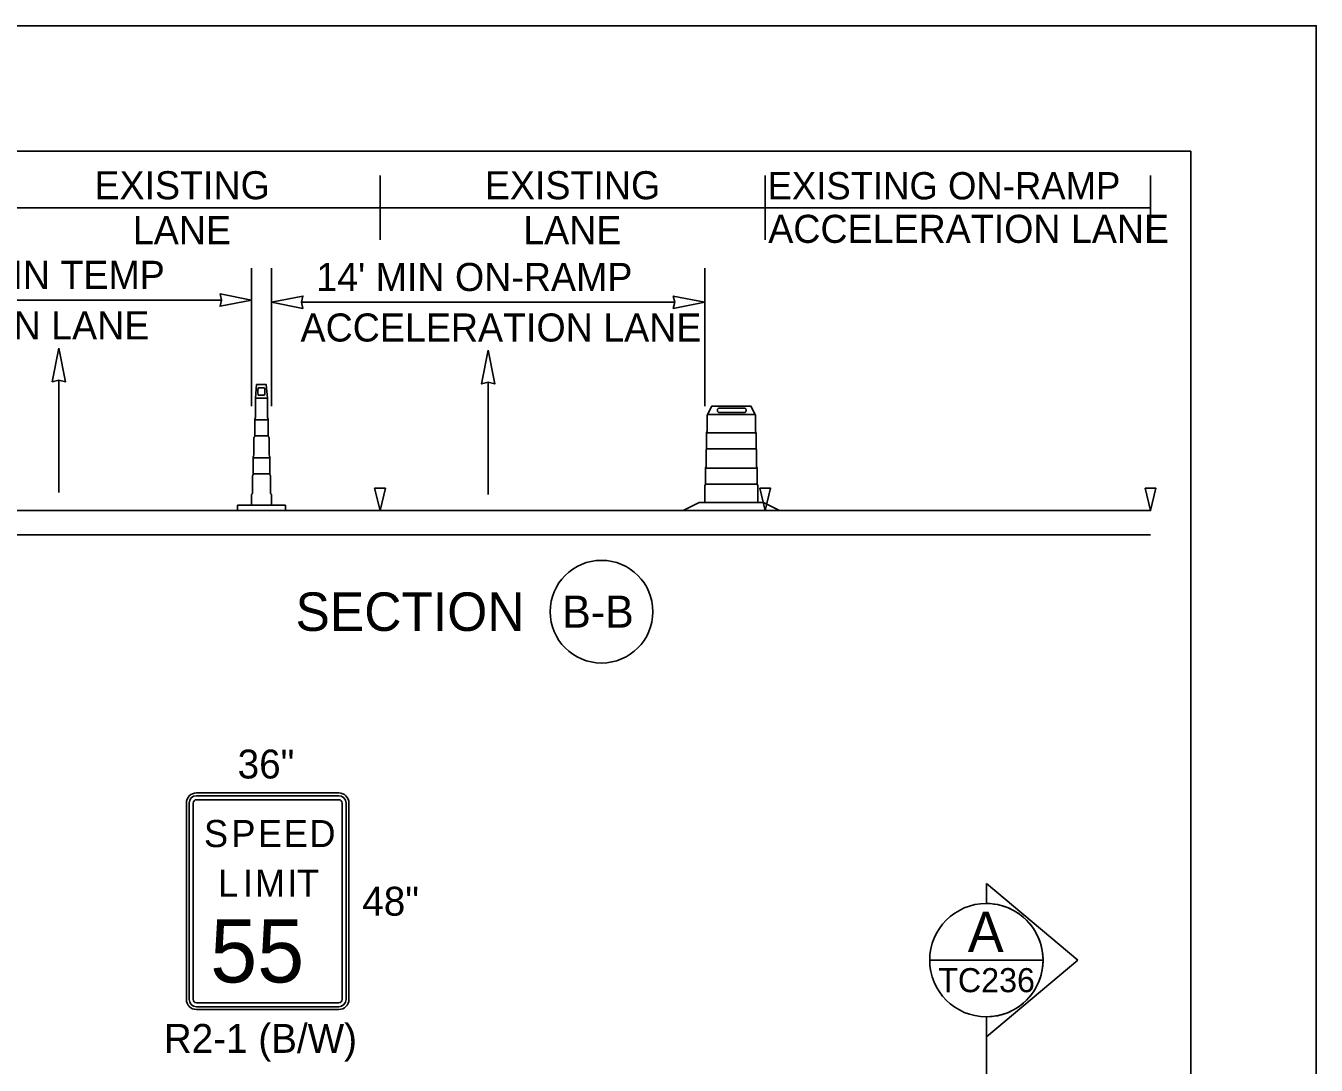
# Model space of a CAD drawing. Extents: x 99999 to 100116, y 99995 to 100013.
# Drawn here: x 100072.847 to 100076.062, y 100008.096 to 100010.687 of the extents above; entities that cross this region are included whole.
import ezdxf

# ---------------------------------------------------------------- set-up
doc = ezdxf.new("R2010")
doc.units = 0
for name, color, linetype in [('SH_GI_PlotLimits', 7, 'Continuous'), ('SH_GI_SheetBorder', 7, 'Continuous'), ('SH_TI_WZSectionCut', 7, 'Continuous'), ('TR_SN_ConstructionSigns', 7, 'Continuous'), ('TR_WZ_ArrowLeftStrRightTurn', 7, 'Continuous'), ('TR_WZ_TallChanDeviceElev', 7, 'Continuous'), ('TR_WZ_TrafficSafetyDrumElev', 7, 'Continuous'), ('TR_WZ_WorkZoneDetails', 7, 'Continuous')]:
    doc.layers.add(name, color=color, linetype=linetype)

msp = doc.modelspace()

# ---------------------------------------------------------------- linework, layer by layer
at = {"layer": 'SH_GI_PlotLimits'}
msp.add_lwpolyline([(100059.0625, 99999.6875), (100076.0625, 99999.6875), (100076.0625, 100010.6875), (100059.0625, 100010.6875)], close=True, dxfattribs=at)
at = {"layer": 'SH_GI_SheetBorder'}
for p, q in [((100060, 100010.375), (100075.75, 100010.375)), ((100075.75, 100010.375), (100075.75, 100000))]:
    msp.add_line(p, q, dxfattribs=at)
at = {"layer": 'SH_TI_WZSectionCut'}
for p, q in [((100073.41, 100009.7388), (100073.41, 100010.0836)), ((100072.525, 100010.0036), (100073.335, 100010.0036)), ((100075.2407, 100008.4993), (100075.2407, 100008.5492)), ((100075.2407, 100008.5492), (100075.4688, 100008.358)), ((100075.4688, 100008.358), (100075.2407, 100008.1669)), ((100075.2407, 100008.1669), (100075.2407, 100008.2168)), ((100075.2407, 100008.1669), (100075.2407, 100006.4389))]:
    msp.add_line(p, q, dxfattribs=at)
msp.add_lwpolyline([(100073.41, 100010.0036), (100073.3314, 100009.9882), (100073.335, 100010.0036), (100073.3314, 100010.019)], close=True, dxfattribs=at)
msp.add_lwpolyline([(100075.0995, 100008.3581), (100075.3819, 100008.3581)], dxfattribs=at)
msp.add_circle((100075.2407, 100008.358), 0.1412, dxfattribs=at)
msp.add_arc((100075.2407, 100008.358), 0.1412, 269.9978, 90.0022, dxfattribs=at)
at = {"layer": 'TR_SN_ConstructionSigns'}
for p, q in [((100073.2728, 100008.7749), (100073.6272, 100008.7749)), ((100073.6272, 100008.7749), (100073.2728, 100008.7749)), ((100073.6272, 100008.7679), (100073.2728, 100008.7679)), ((100073.2728, 100008.758), (100073.6272, 100008.758)), ((100073.2475, 100008.2602), (100073.2475, 100008.7496)), ((100073.2475, 100008.7496), (100073.2475, 100008.2602)), ((100073.2546, 100008.7496), (100073.2546, 100008.2602)), ((100073.2644, 100008.2602), (100073.2644, 100008.7496)), ((100073.6357, 100008.7496), (100073.6357, 100008.2602)), ((100073.6455, 100008.2602), (100073.6455, 100008.7496)), ((100073.6525, 100008.7496), (100073.6525, 100008.2602)), ((100073.6525, 100008.2602), (100073.6525, 100008.7496)), ((100073.6272, 100008.2518), (100073.2728, 100008.2518)), ((100073.2728, 100008.2419), (100073.6272, 100008.2419)), ((100073.6272, 100008.2349), (100073.2728, 100008.2349)), ((100073.2728, 100008.2349), (100073.6272, 100008.2349))]:
    msp.add_line(p, q, dxfattribs=at)
for centre, radius, start, end in [((100073.2728, 100008.7496), 0.0253, 90, 180), ((100073.2728, 100008.7496), 0.0253, 90, 180), ((100073.2728, 100008.7496), 0.0183, 90, 180), ((100073.2728, 100008.7496), 0.00844, 90, 180), ((100073.6272, 100008.7496), 0.0253, 360, 90), ((100073.6272, 100008.7496), 0.0253, 360, 90), ((100073.6272, 100008.7496), 0.0183, 0, 90), ((100073.6272, 100008.7496), 0.00844, 360, 90), ((100073.2728, 100008.2602), 0.0253, 180, 270), ((100073.2728, 100008.2602), 0.0253, 180, 270), ((100073.2728, 100008.2602), 0.0183, 180, 270), ((100073.2728, 100008.2602), 0.00844, 180, 270), ((100073.6272, 100008.2602), 0.0253, 270, 360), ((100073.6272, 100008.2602), 0.0183, 270, 360), ((100073.6272, 100008.2602), 0.00844, 270, 0), ((100073.6272, 100008.2602), 0.0253, 270, 360)]:
    msp.add_arc(centre, radius, start, end, dxfattribs=at)
at = {"layer": 'TR_WZ_ArrowLeftStrRightTurn'}
for p, q in [((100072.93, 100009.8039), (100072.93, 100009.524)), ((100073.9994, 100009.7986), (100073.9994, 100009.5187))]:
    msp.add_line(p, q, dxfattribs=at)
for points in [[(100072.93, 100009.884), (100072.9135, 100009.8), (100072.93, 100009.8039), (100072.9465, 100009.8)], [(100073.9994, 100009.8787), (100073.9829, 100009.7947), (100073.9994, 100009.7986), (100074.0159, 100009.7947)]]:
    msp.add_lwpolyline(points, close=True, dxfattribs=at)
at = {"layer": 'TR_WZ_TallChanDeviceElev'}
for p, q in [((100073.4422, 100009.7848), (100073.4266, 100009.7848)), ((100073.4494, 100009.7588), (100073.42, 100009.7588)), ((100073.42, 100009.7588), (100073.4494, 100009.7588)), ((100073.42, 100009.7588), (100073.4494, 100009.7588)), ((100073.4266, 100009.767), (100073.4422, 100009.767)), ((100073.4178, 100009.7051), (100073.4515, 100009.7051)), ((100073.4178, 100009.6655), (100073.4178, 100009.7051)), ((100073.4515, 100009.7051), (100073.4515, 100009.6655)), ((100073.4515, 100009.6655), (100073.4178, 100009.6655)), ((100073.4139, 100009.5707), (100073.4139, 100009.6103)), ((100073.4139, 100009.6103), (100073.4555, 100009.6103)), ((100073.4555, 100009.6103), (100073.4555, 100009.5707)), ((100073.4555, 100009.5707), (100073.4139, 100009.5707)), ((100073.3747, 100009.4788), (100073.3747, 100009.492)), ((100073.4947, 100009.4788), (100073.3747, 100009.4788)), ((100073.4947, 100009.492), (100073.4947, 100009.4788))]:
    msp.add_line(p, q, dxfattribs=at)
for points in [[(100073.4494, 100009.7588), (100073.4467, 100009.793), (100073.4225, 100009.793), (100073.42, 100009.7588)], [(100073.4515, 100009.7051), (100073.4178, 100009.7051), (100073.4178, 100009.6655), (100073.4515, 100009.6655)], [(100073.4555, 100009.6103), (100073.4139, 100009.6103), (100073.4139, 100009.5707), (100073.4555, 100009.5707)]]:
    msp.add_lwpolyline(points, close=True, dxfattribs=at)
for points in [[(100073.4198, 100009.7106), (100073.4198, 100009.7555)], [(100073.4198, 100009.7106), (100073.4198, 100009.7555)], [(100073.4496, 100009.7555), (100073.4496, 100009.7106)], [(100073.4496, 100009.7555), (100073.4496, 100009.7106)], [(100073.4178, 100009.6632), (100073.4178, 100009.7074)], [(100073.4178, 100009.6632), (100073.4178, 100009.7074)], [(100073.4515, 100009.7074), (100073.4515, 100009.6632)], [(100073.4515, 100009.7074), (100073.4515, 100009.6632)], [(100073.4159, 100009.6158), (100073.4159, 100009.66)], [(100073.4159, 100009.6158), (100073.4159, 100009.66)], [(100073.4535, 100009.66), (100073.4535, 100009.6158)], [(100073.4535, 100009.66), (100073.4535, 100009.6158)], [(100073.4139, 100009.5685), (100073.4139, 100009.6125)], [(100073.4139, 100009.5685), (100073.4139, 100009.6125)], [(100073.4555, 100009.6125), (100073.4555, 100009.5685)], [(100073.4555, 100009.6125), (100073.4555, 100009.5685)], [(100073.412, 100009.5212), (100073.412, 100009.5653)], [(100073.412, 100009.5212), (100073.412, 100009.5653)], [(100073.4574, 100009.5653), (100073.4574, 100009.5212)], [(100073.4574, 100009.5653), (100073.4574, 100009.5212)], [(100073.4594, 100009.492), (100073.41, 100009.492), (100073.41, 100009.518)], [(100073.4594, 100009.492), (100073.41, 100009.492), (100073.41, 100009.518)], [(100073.4594, 100009.518), (100073.4594, 100009.492)], [(100073.4594, 100009.518), (100073.4594, 100009.492)], [(100073.3747, 100009.492), (100073.41, 100009.492), (100073.4594, 100009.492), (100073.4947, 100009.492)]]:
    msp.add_lwpolyline(points, dxfattribs=at)
for centre, major_axis, ratio, start_param, end_param in [((100073.4266, 100009.7759), (0, 0.00891), 0.07945, 0, 3.141593), ((100073.4422, 100009.7759), (0, 0.00891), 0.07945, 3.141593, 6.283185), ((100073.42, 100009.7548), (0, 0.00412), 0.059356, 0.177149, 1.393647), ((100073.42, 100009.7548), (0, 0.00412), 0.059356, 0.177149, 1.393647), ((100073.4493, 100009.7548), (0, 0.00412), 0.059356, 4.889538, 6.106036), ((100073.4493, 100009.7548), (0, 0.00412), 0.059356, 4.889538, 6.106036), ((100073.4214, 100009.7047), (0, 0.00651), 0.609371, 0.4288, 1.141997), ((100073.4214, 100009.7047), (0, 0.00651), 0.609371, 0.4288, 1.141997), ((100073.4479, 100009.7047), (0, 0.00651), 0.609371, 5.141189, 5.854386), ((100073.4479, 100009.7047), (0, 0.00651), 0.609371, 5.141189, 5.854386), ((100073.4195, 100009.6573), (0, 0.00651), 0.609371, 0.4288, 1.141997), ((100073.4195, 100009.6573), (0, 0.00651), 0.609371, 0.4288, 1.141997), ((100073.4499, 100009.6573), (0, 0.00651), 0.609371, 5.141189, 5.854386), ((100073.4499, 100009.6573), (0, 0.00651), 0.609371, 5.141189, 5.854386), ((100073.4175, 100009.6098), (0, 0.00651), 0.609371, 0.4288, 1.141997), ((100073.4175, 100009.6098), (0, 0.00651), 0.609371, 0.4288, 1.141997), ((100073.4519, 100009.6098), (0, 0.00651), 0.609371, 5.141189, 5.854386), ((100073.4519, 100009.6098), (0, 0.00651), 0.609371, 5.141189, 5.854386), ((100073.4156, 100009.5625), (0, 0.00651), 0.609371, 0.4288, 1.141997), ((100073.4156, 100009.5625), (0, 0.00651), 0.609371, 0.4288, 1.141997), ((100073.4538, 100009.5625), (0, 0.00651), 0.609371, 5.141189, 5.854386), ((100073.4538, 100009.5625), (0, 0.00651), 0.609371, 5.141189, 5.854386), ((100073.4136, 100009.5153), (0, 0.00651), 0.609371, 0.4288, 1.141997), ((100073.4136, 100009.5153), (0, 0.00651), 0.609371, 0.4288, 1.141997), ((100073.4558, 100009.5153), (0, 0.00651), 0.609371, 5.141189, 5.854386), ((100073.4558, 100009.5153), (0, 0.00651), 0.609371, 5.141189, 5.854386)]:
    msp.add_ellipse(centre, major_axis=major_axis, ratio=ratio, start_param=start_param, end_param=end_param, dxfattribs=at)
at = {"layer": 'TR_WZ_TrafficSafetyDrumElev'}
for p, q in [((100074.5737, 100009.734), (100074.6391, 100009.734)), ((100074.6391, 100009.7236), (100074.5737, 100009.7236)), ((100074.5461, 100009.7188), (100074.6645, 100009.7188)), ((100074.5461, 100009.7188), (100074.6645, 100009.7188)), ((100074.5438, 100009.6724), (100074.6668, 100009.6724)), ((100074.5438, 100009.6325), (100074.5438, 100009.6724)), ((100074.6668, 100009.6724), (100074.6668, 100009.6325)), ((100074.6668, 100009.6325), (100074.5438, 100009.6325)), ((100074.5409, 100009.5844), (100074.6697, 100009.5844)), ((100074.5409, 100009.5445), (100074.5409, 100009.5844)), ((100074.6697, 100009.5844), (100074.6697, 100009.5445)), ((100074.6697, 100009.5445), (100074.5409, 100009.5445))]:
    msp.add_line(p, q, dxfattribs=at)
for points in [[(100074.6645, 100009.7188), (100074.654, 100009.7388), (100074.5566, 100009.7388), (100074.5461, 100009.7188)], [(100074.4853, 100009.4788), (100074.5255, 100009.4988), (100074.6851, 100009.4988), (100074.7253, 100009.4788)]]:
    msp.add_lwpolyline(points, close=True, dxfattribs=at)
for points in [[(100074.5453, 100009.676), (100074.5453, 100009.7172)], [(100074.5453, 100009.676), (100074.5453, 100009.7172)], [(100074.6653, 100009.7172), (100074.6653, 100009.676)], [(100074.6653, 100009.7172), (100074.6653, 100009.676)], [(100074.5438, 100009.632), (100074.5438, 100009.673)], [(100074.5438, 100009.632), (100074.5438, 100009.673)], [(100074.6668, 100009.673), (100074.6668, 100009.632)], [(100074.6668, 100009.673), (100074.6668, 100009.632)], [(100074.5423, 100009.5879), (100074.5423, 100009.629)], [(100074.5423, 100009.5879), (100074.5423, 100009.629)], [(100074.6682, 100009.629), (100074.6682, 100009.5879)], [(100074.6682, 100009.629), (100074.6682, 100009.5879)], [(100074.5409, 100009.5439), (100074.5409, 100009.5849)], [(100074.5409, 100009.5439), (100074.5409, 100009.5849)], [(100074.6697, 100009.5849), (100074.6697, 100009.5439)], [(100074.6697, 100009.5849), (100074.6697, 100009.5439)], [(100074.6712, 100009.5409), (100074.6712, 100009.4988), (100074.5394, 100009.4988), (100074.5394, 100009.5409)], [(100074.6712, 100009.5409), (100074.6712, 100009.4988), (100074.5394, 100009.4988), (100074.5394, 100009.5409)]]:
    msp.add_lwpolyline(points, dxfattribs=at)
for centre, major_axis, ratio, start_param, end_param in [((100074.5737, 100009.7288), (0, 0.0052), 0.570305, 0, 3.141593), ((100074.6391, 100009.7288), (0, 0.0052), 0.570305, 3.141593, 6.283185), ((100074.5463, 100009.7168), (0, 0.00199), 0.493438, 0.177149, 1.393647), ((100074.5463, 100009.7168), (0, 0.00199), 0.493438, 0.177149, 1.393647), ((100074.6643, 100009.7168), (0, 0.00199), 0.493438, 4.889538, 6.106036), ((100074.6643, 100009.7168), (0, 0.00199), 0.493438, 4.889538, 6.106036), ((100074.5465, 100009.6705), (0, 0.00606), 0.493438, 0.4288, 1.141997), ((100074.5465, 100009.6705), (0, 0.00606), 0.493438, 0.4288, 1.141997), ((100074.664, 100009.6705), (0, 0.00606), 0.493438, 5.141189, 5.854386), ((100074.664, 100009.6705), (0, 0.00606), 0.493438, 5.141189, 5.854386), ((100074.5451, 100009.6265), (0, 0.00606), 0.493438, 0.4288, 1.141997), ((100074.5451, 100009.6265), (0, 0.00606), 0.493438, 0.4288, 1.141997), ((100074.6655, 100009.6265), (0, 0.00606), 0.493438, 5.141189, 5.854386), ((100074.6655, 100009.6265), (0, 0.00606), 0.493438, 5.141189, 5.854386), ((100074.5436, 100009.5824), (0, 0.00606), 0.493438, 0.4288, 1.141997), ((100074.5436, 100009.5824), (0, 0.00606), 0.493438, 0.4288, 1.141997), ((100074.667, 100009.5824), (0, 0.00606), 0.493438, 5.141189, 5.854386), ((100074.667, 100009.5824), (0, 0.00606), 0.493438, 5.141189, 5.854386), ((100074.5421, 100009.5384), (0, 0.00606), 0.493438, 0.4288, 1.141997), ((100074.5421, 100009.5384), (0, 0.00606), 0.493438, 0.4288, 1.141997), ((100074.6685, 100009.5384), (0, 0.00606), 0.493438, 5.141189, 5.854386), ((100074.6685, 100009.5384), (0, 0.00606), 0.493438, 5.141189, 5.854386)]:
    msp.add_ellipse(centre, major_axis=major_axis, ratio=ratio, start_param=start_param, end_param=end_param, dxfattribs=at)
at = {"layer": 'TR_WZ_WorkZoneDetails'}
for p, q in [((100073.73, 100010.154), (100073.73, 100010.314)), ((100074.69, 100010.154), (100074.69, 100010.314)), ((100075.65, 100010.154), (100075.65, 100010.314)), ((100072.77, 100010.234), (100073.73, 100010.234)), ((100073.73, 100010.234), (100074.69, 100010.234)), ((100074.69, 100010.234), (100075.65, 100010.234)), ((100073.4594, 100009.7388), (100073.4594, 100010.0836)), ((100074.5394, 100009.7388), (100074.5394, 100010.0836)), ((100074.4644, 100009.9983), (100073.5344, 100009.9983)), ((100075.65, 100009.4787), (100072.45, 100009.4787)), ((100075.65, 100009.4187), (100072.45, 100009.4187))]:
    msp.add_line(p, q, dxfattribs=at)
for points in [[(100073.4594, 100009.9983), (100073.538, 100009.9829), (100073.5344, 100009.9983), (100073.538, 100010.0137)], [(100074.5394, 100009.9983), (100074.4608, 100009.9829), (100074.4644, 100009.9983), (100074.4608, 100010.0137)], [(100073.73, 100009.4787), (100073.7166, 100009.5346), (100073.7433, 100009.5346)], [(100074.69, 100009.4787), (100074.6766, 100009.5346), (100074.7033, 100009.5346)], [(100075.65, 100009.4787), (100075.6366, 100009.5346), (100075.6633, 100009.5346)]]:
    msp.add_lwpolyline(points, close=True, dxfattribs=at)
for points in [[(100073.7433, 100009.5346), (100073.7166, 100009.5346), (100073.73, 100009.4787), (100073.7433, 100009.5346)], [(100074.7033, 100009.5346), (100074.6766, 100009.5346), (100074.69, 100009.4787), (100074.7033, 100009.5346)], [(100075.6633, 100009.5346), (100075.6366, 100009.5346), (100075.65, 100009.4787), (100075.6633, 100009.5346)]]:
    msp.add_lwpolyline(points, dxfattribs=at)
msp.add_circle((100074.2819, 100009.2268), 0.128, dxfattribs=at)

# ---------------------------------------------------------------- texts
at = {"layer": 'SH_TI_WZSectionCut'}
for s, height, rotation, p in [('A', 0.1, 0.01, (100075.1945, 100008.3787)), ('TC236', 0.06, 360, (100075.1209, 100008.2781))]:
    msp.add_text(s, height=height, rotation=rotation, dxfattribs=at).set_placement(p)
at = {"layer": 'TR_SN_ConstructionSigns'}
for s, height, p in [('36"', 0.072, (100073.3753, 100008.8109)), ('S', 0.0675, (100073.2914, 100008.6399)), ('P', 0.0675, (100073.3596, 100008.6399)), ('E', 0.0675, (100073.4257, 100008.6399)), ('E', 0.0675, (100073.4899, 100008.6399)), ('D', 0.0675, (100073.554, 100008.6399)), ('L', 0.0675, (100073.3265, 100008.5162)), ('I', 0.0675, (100073.3886, 100008.5162)), ('M', 0.0675, (100073.4183, 100008.5162)), ('I', 0.0675, (100073.4993, 100008.5162)), ('T', 0.0675, (100073.5229, 100008.5162)), ('48"', 0.072, (100073.6858, 100008.4689)), ('55', 0.1575, (100073.3068, 100008.3024)), ('R2-1 (B/W)', 0.072, (100073.1913, 100008.1269))]:
    msp.add_text(s, height=height, rotation=360, dxfattribs=at).set_placement(p)
at = {"layer": 'TR_WZ_WorkZoneDetails'}
for s, height, p in [('EXISTING', 0.07, (100073.0185, 100010.255)), ('EXISTING', 0.07, (100073.9912, 100010.255)), ('EXISTING ON-RAMP', 0.068, (100074.6955, 100010.2547)), ('LANE', 0.07, (100073.1142, 100010.143)), ('LANE', 0.07, (100074.0869, 100010.143)), ('ACCELERATION LANE', 0.07, (100074.6973, 100010.1463)), ("12' MIN TEMP", 0.07, (100072.5882, 100010.0316)), ("14' MIN ON-RAMP", 0.07, (100073.5712, 100010.0263)), ('OPEN LANE', 0.07, (100072.6194, 100009.9056)), ('ACCELERATION LANE', 0.07, (100073.532, 100009.9003))]:
    msp.add_text(s, height=height, dxfattribs=at).set_placement(p)
for s, height, p in [('SECTION', 0.096, (100073.5194, 100009.1788)), ('B-B', 0.08, (100074.1839, 100009.1868))]:
    msp.add_text(s, height=height, rotation=360, dxfattribs=at).set_placement(p)

doc.saveas('drawing.dxf')
